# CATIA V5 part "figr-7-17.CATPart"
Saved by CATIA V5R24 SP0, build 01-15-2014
Part number: Part2
Bounding box of the stored display mesh (mm): x -50 to 50, y -65 to 65, z 0 to 28
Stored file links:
  D:\KAVITA\CATIA V5-6R2014 Project_ Kavita\CATIA V5-6R2014_partfiles\Partfiles\c07_catia_v5-6r2014_prt\figr-7-17.CATPart
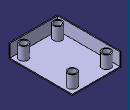
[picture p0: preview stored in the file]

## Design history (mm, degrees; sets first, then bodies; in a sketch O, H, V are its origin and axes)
Body1 (main body)
  Sketch1 on xy-plane, origin (0, 0, 0), H (1, 0, 0), V (0, 1, 0)
    line L1 (-50, 65) -> (50, 65)
    line L2 (50, 65) -> (50, -65)
    line L3 (50, -65) -> (-50, -65)
    line L4 (-50, -65) -> (-50, 65)
    axis line L5 (50, -65) -> (-50, 65)
    length L3 = 100
    length L2 = 130
    horizontal: L1 H, L3 H
    vertical: L2 V, L4 V
    midpoint: O L5
  Pad1: profile Sketch1, direction (0, 0, 1), length 28
  Sketch2 on face of Pad1, origin (25.9302, -33.7092, 28), H (1, 0, 0), V (0, 1, 0)
    point P1 (9.0698, -16.2908)
    reference projected line E1 (-75.9302, -31.2908) -> (24.0698, -31.2908) from edge [face of Pad1 | face of Pad1]
    reference projected line E2 (24.0698, -31.2908) -> (24.0698, 98.7092) from edge [face of Pad1 | face of Pad1]
    distance P1 E1 = 15
    distance P1 E2 = 15
  Hole1: placed by Sketch2, at (35, -50, 28) direction (0, 0, -1), diameter 14, through (limit type 3)
  RectPattern1: of Hole1, direction 1 instances 2, spacing 100, along edge [face of Pad1 | face of Pad1], direction 2 instances 2, spacing 70, along edge [face of Pad1 | face of Pad1]
  Shell1: ExtOffset 0, Face (face of Pad1; face of Pad1; face of Pad1), IntOffset 2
